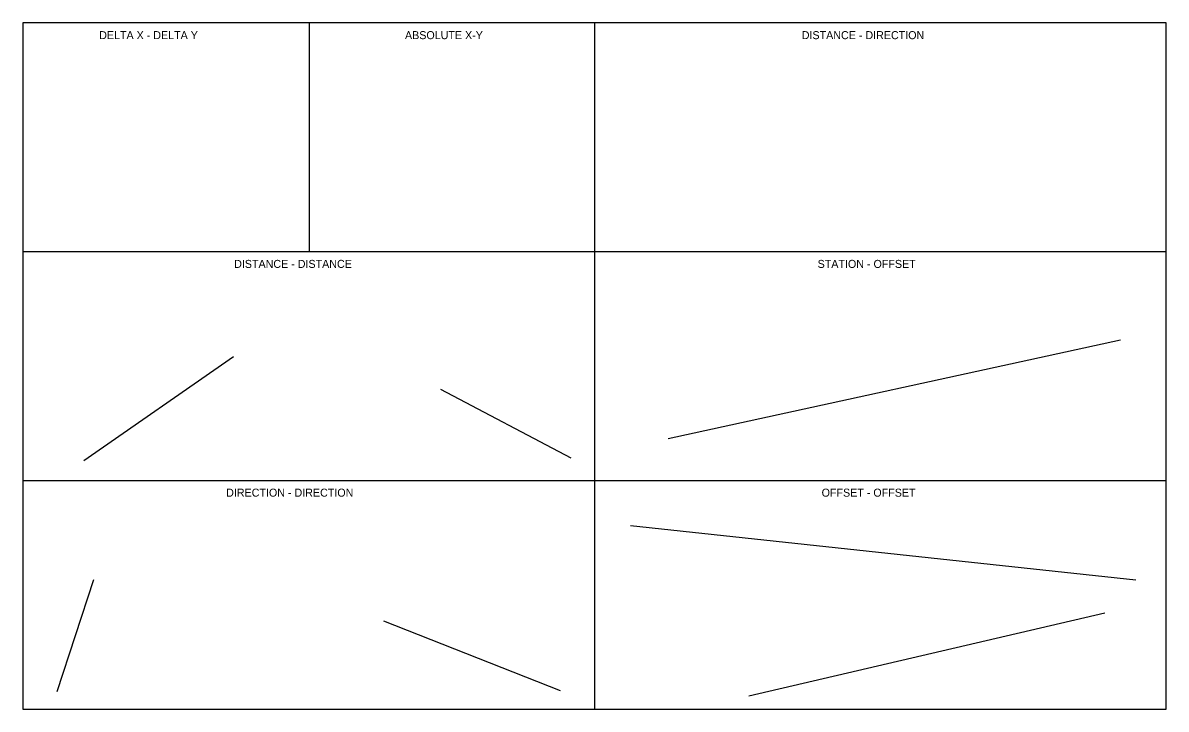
# Model space of a CAD drawing. Extents: x 0 to 3000, y 0 to 1800.
import ezdxf

# ---------------------------------------------------------------- set-up
doc = ezdxf.new("R2010")
doc.units = 0
doc.layers.add('Level 1', color=7, linetype='Continuous')

msp = doc.modelspace()

# ---------------------------------------------------------------- linework, layer by layer
at = {"layer": 'Level 1'}
for p, q in [((751.6, 1799.2), (751.6, 1200)), ((1500, 1800), (1500, 0)), ((0, 1200), (3000, 1200)), ((1693.5, 709.8), (2880.5, 968.6)), ((159.9, 651.9), (552.5, 925.3)), ((1095.9, 838.9), (1437.5, 659.5)), ((0, 600), (3000, 600)), ((1594.4, 481.5), (2920.6, 339.2)), ((89.6, 46.3), (186, 340.4)), ((2839, 251.9), (1904.6, 33.9)), ((1410.9, 47.9), (947.3, 230.7))]:
    msp.add_line(p, q, dxfattribs=at)
msp.add_lwpolyline([(0, 0), (3000, 0), (3000, 1800), (0, 1800)], close=True, dxfattribs=at)

# ---------------------------------------------------------------- texts
for s, p in [('DELTA X - DELTA Y', (200.2, 1757.3)), ('ABSOLUTE X-Y', (1002.7, 1757.3)), ('DISTANCE - DIRECTION', (2043.9, 1757.3)), ('DISTANCE - DISTANCE', (554.4, 1157.3)), ('STATION - OFFSET', (2085.5, 1157.3)), ('DIRECTION - DIRECTION', (533.4, 557.3)), ('OFFSET - OFFSET', (2096, 557.3))]:
    msp.add_text(s, height=21, dxfattribs=at).set_placement(p)

doc.saveas('drawing.dxf')
